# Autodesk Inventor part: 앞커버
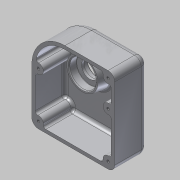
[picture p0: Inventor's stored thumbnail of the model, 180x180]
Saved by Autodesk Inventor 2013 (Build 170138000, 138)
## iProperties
Created: 2015-10
Part Number: 앞커버
Material: 알루미늄 6061
Document SubType Name: Modeling
Designer: mduedu
Density: 2.71 g/cm^3
Mass: 307.08 g
Surface Area: 494.818 cm^2
Volume: 113.314 cm^3
Author: mduedu
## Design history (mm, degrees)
sketch "스케치1"
  geometry: L1 (0, 40)-(60, 40); L2 (60, 40)-(60, -63); L3 (60, -63)-(-40, -63); L4 (-40, -63)-(-40, 0); A1 r 40 centre (0, 0) between (0, 40) and (-40, 0); 1 further point
  constraints: 8 end point, 2 point on circle, 2 tangent, 1 centre point, 1 coincident, 1 horizontal, 1 parallel, 1 perpendicular, 1 vertical
  dimensions: "d0" = 40 radius of A1; "d1" = 103 distance of L1.end L2.end; "d2" = 100 distance of L2.end L3.end
extrude "돌출2" new body sketch "스케치1" distance "d8" = 40; taper "d9" = 0 deg
fillet "모깎기3" dims "d10" = 8
fillet "모깎기4" dims "d11" = 8
feature "쉘2" dims "d12" = 4
sketch "스케치2"
  geometry: C1 r 21.5 at (32, 55); 1 further point
  constraints: 1 centre point, 1 coincident
  dimensions: "d13" = 43 diameter of C1
extrude "돌출3" join sketch "스케치2" distance "d14" = 15; taper "d15" = 0 deg
hole "구멍1" diameter "d18" = 32; stored, may be unused: countersink angle "d22" = 90 deg, drill point angle "d24" = 0 deg; dims "d16" = 10, "d17" = 10, "d19" = 6, "d20" = 4, "d21" = 2, "d23" = 9
hole "구멍2" diameter "d27" = 20; stored, may be unused: countersink angle "d31" = 90 deg, drill point angle "d33" = 0 deg; dims "d25" = 10, "d26" = 10, "d28" = 6, "d29" = 4, "d30" = 2, "d32" = 3
hole "구멍3" diameter "d36" = 25; stored, may be unused: countersink angle "d40" = 90 deg, drill point angle "d42" = 0 deg; dims "d34" = 10, "d35" = 10, "d37" = 6, "d38" = 4, "d39" = 2, "d41" = 3
chamfer "모따기1" distance "d43" = 1; stored, may be unused: second distance "d44" = 2, angle "d45" = 45 deg
feature "면 기울기1" dims angle "d46" = 10 deg
sketch "스케치3"
  geometry: L1 (-40, 0)-(-40, -55) reference; L2 (60, -55)-(60, 32) reference; L3 (-40, 0)-(60, 0); C1 r 6 at (52, 32); C2 r 6 at (52, -55); C3 r 6 at (-32, -55); C4 r 6 at (52, 0); C5 r 6 at (-32, 0); A1 r 8 centre (52, 32) between (60, 32) and (52, 40) reference; A2 r 8 centre (52, -55) between (52, -63) and (60, -55) reference; A3 r 8 centre (-32, -55) between (-40, -55) and (-32, -63) reference; 1 further point
  constraints: 5 centre point, 4 equal radius, 3 coincident, 3 point on line, 2 end point, 2 vertical alignment, 1 perpendicular
  dimensions: "d47" = 6 radius of C1
extrude "돌출4" join sketch "스케치3" stored distance "d49" = 15; taper "d50" = 0 deg
fillet "모깎기5" dims "d51" = 3
fillet "모깎기6" dims "d52" = 3
sketch "스케치4"
  geometry: A1 r 6 centre (-32, 0) between (-32.667, -5.963) and (-31.833, 5.998) reference; A2 r 6 centre (52, 32) between (46.037, 32.667) and (52.667, 26.037) reference; A3 r 6 centre (52, 0) between (52.667, 5.963) and (52.667, -5.963) reference; A4 r 6 centre (52, -55) between (52.667, -49.037) and (46.037, -55.667) reference; A5 r 6 centre (-32, -55) between (-26.037, -55.667) and (-32.667, -49.037) reference; 6 further points
  constraints: 5 coincident
hole "구멍4" sketch "스케치4" at (-32, 0), (52, 32), (52, 0), (52, -55), (-32, -55) diameter "d53" = 3.242; stored, may be unused: countersink angle "d57" = 90 deg, drill point angle "d59" = 118 deg; dims "d54" = 12, "d55" = 4, "d56" = 2, "d58" = 14
sketch "스케치5"
  geometry: L1 (-52, -63)-(32, -63) reference; L2 (-60, 32)-(-60, -55) reference; 2 further points
  constraints: 1 other
  dimensions: "d60" = 20 distance from line of point (-10, -43) L1; "d61" = 50 distance from line of point (-10, -43) L2
feature "엠보싱1" sketch "스케치5" dims "d13" = 43, "d62" = 0.5, "d63" = 0
fillet "모깎기7" dims "d64" = 0.3
node "솔리드2"
